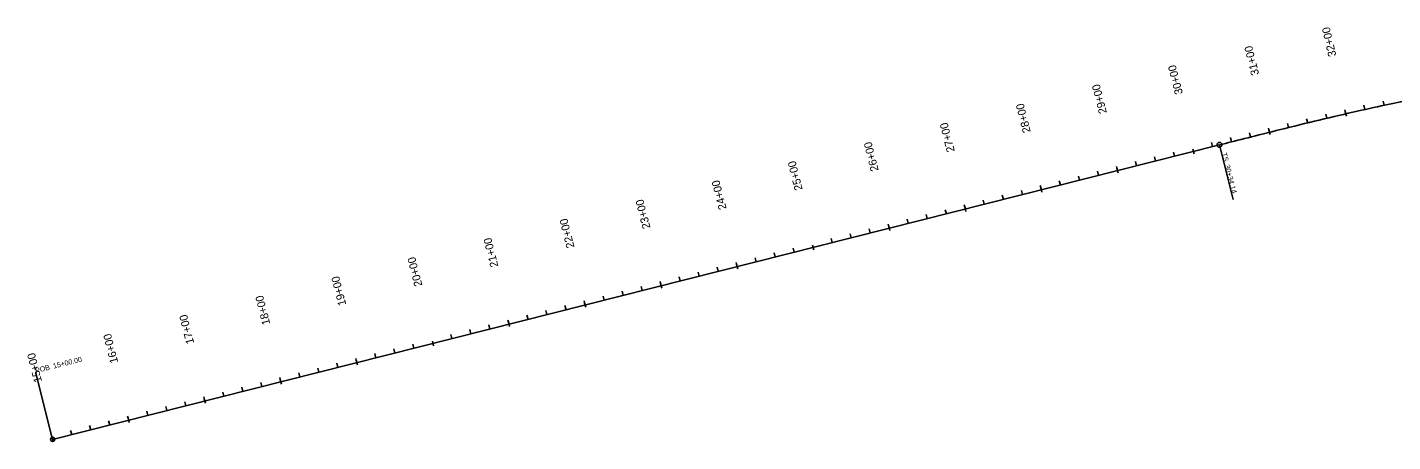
# Model space of a CAD drawing. Extents: x 21446797 to 21450291, y 8416521 to 8417382.
# Drawn here: x 21446797 to 21448538, y 8416521 to 8417049 of the extents above; entities that cross this region are included whole.
import ezdxf

# ---------------------------------------------------------------- set-up
doc = ezdxf.new("R2010")
doc.units = 0
for name, color, linetype in [('Default', 7, 'Continuous'), ('Terrain', 7, 'Continuous'), ('TextAlignment', 7, 'Continuous'), ('TextAlignmentLrg', 7, 'Continuous'), ('TextAlignmentSml', 7, 'Continuous')]:
    doc.layers.add(name, color=color, linetype=linetype)

msp = doc.modelspace()

# ---------------------------------------------------------------- linework, layer by layer
at = {"layer": 'Default'}
msp.add_line((21446829.6, 8416523.7), (21448317.1, 8416899.4), dxfattribs=at)
msp.add_open_spline([(21448317.1, 8416899.4), (21448327.1, 8416901.9), (21448347.3, 8416907), (21448387.6, 8416917.2), (21448438, 8416929.6), (21448488.6, 8416941.5), (21448529.2, 8416950.5), (21448549.5, 8416954.8), (21448559.7, 8416956.9)], degree=3, dxfattribs=at)
at = {"layer": 'Terrain'}
msp.add_line((21446829.6, 8416523.7), (21448317.1, 8416899.4), dxfattribs=at)
msp.add_open_spline([(21448317.1, 8416899.4), (21448327.1, 8416901.9), (21448347.3, 8416907), (21448387.6, 8416917.2), (21448438, 8416929.6), (21448488.6, 8416941.5), (21448529.2, 8416950.5), (21448549.5, 8416954.8), (21448559.7, 8416956.9)], degree=3, dxfattribs=at)
at = {"layer": 'TextAlignment'}
for p, q in [((21448317.1, 8416899.4), (21448334.7, 8416829.6)), ((21446829.6, 8416523.7), (21446808.3, 8416608))]:
    msp.add_line(p, q, dxfattribs=at)
for centre, radius in [((21448317.1, 8416899.4), 3.12), ((21446829.6, 8416523.7), 2.67)]:
    msp.add_circle(centre, radius, dxfattribs=at)
at = {"layer": 'TextAlignmentLrg'}
for p, q in [((21448478.1, 8416939), (21448476.9, 8416944.3)), ((21448380.9, 8416915.5), (21448379.6, 8416920.8)), ((21448283.2, 8416894), (21448284.7, 8416888.1)), ((21448187, 8416866.6), (21448185.7, 8416871.8)), ((21448090, 8416842.1), (21448088.7, 8416847.4)), ((21447993.1, 8416817.6), (21447991.8, 8416822.9)), ((21447896.1, 8416793.1), (21447894.8, 8416798.4)), ((21447798.4, 8416771.6), (21447799.9, 8416765.6)), ((21447702.2, 8416744.1), (21447700.9, 8416749.4)), ((21447605.3, 8416719.6), (21447603.9, 8416724.9)), ((21447508.3, 8416695.1), (21447507, 8416700.4)), ((21447411.4, 8416670.6), (21447410, 8416675.9)), ((21447313.7, 8416649.1), (21447315.2, 8416643.2)), ((21447217.5, 8416621.7), (21447216.1, 8416626.9)), ((21447120.5, 8416597.2), (21447119.2, 8416602.5)), ((21447023.5, 8416572.7), (21447022.2, 8416578)), ((21446926.6, 8416548.2), (21446925.2, 8416553.5)), ((21446828.9, 8416526.7), (21446830.4, 8416520.7))]:
    msp.add_line(p, q, dxfattribs=at)
at = {"layer": 'TextAlignmentSml'}
for p, q in [((21448502.5, 8416944.5), (21448501.3, 8416949.9)), ((21448526.9, 8416950), (21448525.7, 8416955.3)), ((21448429.5, 8416927.4), (21448428.2, 8416932.7)), ((21448453.8, 8416933.3), (21448452.5, 8416938.6)), ((21448477.4, 8416942), (21448478.8, 8416936)), ((21448356.7, 8416909.4), (21448355.3, 8416914.7)), ((21448380.2, 8416918.4), (21448381.7, 8416912.5)), ((21448405.2, 8416921.5), (21448403.9, 8416926.8)), ((21448308.2, 8416897.2), (21448306.9, 8416902.5)), ((21448332.4, 8416903.3), (21448331.1, 8416908.6)), ((21448211.2, 8416872.7), (21448209.9, 8416878)), ((21448235.5, 8416878.8), (21448234.1, 8416884.1)), ((21448259.7, 8416884.9), (21448258.4, 8416890.2)), ((21448283.2, 8416894), (21448284.7, 8416888.1)), ((21448138.5, 8416854.3), (21448137.2, 8416859.6)), ((21448162.8, 8416860.4), (21448161.4, 8416865.7)), ((21448186.3, 8416869.5), (21448187.8, 8416863.6)), ((21448089.3, 8416845), (21448090.8, 8416839.1)), ((21448114.3, 8416848.2), (21448112.9, 8416853.5)), ((21448017.3, 8416823.7), (21448016, 8416829)), ((21448041.6, 8416829.8), (21448040.2, 8416835.1)), ((21448065.8, 8416835.9), (21448064.5, 8416841.2)), ((21447944.6, 8416805.3), (21447943.3, 8416810.6)), ((21447968.9, 8416811.4), (21447967.5, 8416816.7)), ((21447992.3, 8416820.5), (21447993.8, 8416814.6)), ((21447871.9, 8416787), (21447870.6, 8416792.3)), ((21447895.4, 8416796), (21447896.9, 8416790.1)), ((21447920.4, 8416799.2), (21447919, 8416804.5)), ((21447823.4, 8416774.7), (21447822.1, 8416780)), ((21447847.7, 8416780.8), (21447846.3, 8416786.1)), ((21447726.5, 8416750.2), (21447725.1, 8416755.5)), ((21447750.7, 8416756.3), (21447749.4, 8416761.6)), ((21447774.9, 8416762.5), (21447773.6, 8416767.8)), ((21447798.4, 8416771.6), (21447799.9, 8416765.6)), ((21447678, 8416738), (21447676.7, 8416743.3)), ((21447701.5, 8416747.1), (21447703, 8416741.1)), ((21447604.5, 8416722.6), (21447606, 8416716.6)), ((21447629.5, 8416725.7), (21447628.2, 8416731)), ((21447653.7, 8416731.9), (21447652.4, 8416737.2)), ((21447532.6, 8416701.2), (21447531.2, 8416706.5)), ((21447556.8, 8416707.4), (21447555.5, 8416712.7)), ((21447581, 8416713.5), (21447579.7, 8416718.8)), ((21447459.8, 8416682.9), (21447458.5, 8416688.2)), ((21447484.1, 8416689), (21447482.7, 8416694.3)), ((21447507.6, 8416698.1), (21447509.1, 8416692.2)), ((21447387.1, 8416664.5), (21447385.8, 8416669.8)), ((21447410.6, 8416673.6), (21447412.1, 8416667.7)), ((21447435.6, 8416676.8), (21447434.3, 8416682.1)), ((21447338.6, 8416652.3), (21447337.3, 8416657.6)), ((21447362.9, 8416658.4), (21447361.5, 8416663.7)), ((21447241.7, 8416627.8), (21447240.4, 8416633.1)), ((21447265.9, 8416633.9), (21447264.6, 8416639.2)), ((21447290.2, 8416640), (21447288.8, 8416645.3)), ((21447313.7, 8416649.1), (21447315.2, 8416643.2)), ((21447193.2, 8416615.5), (21447191.9, 8416620.8)), ((21447216.7, 8416624.6), (21447218.2, 8416618.7)), ((21447119.7, 8416600.1), (21447121.2, 8416594.2)), ((21447144.7, 8416603.3), (21447143.4, 8416608.6)), ((21447169, 8416609.4), (21447167.6, 8416614.7)), ((21447047.8, 8416578.8), (21447046.4, 8416584.1)), ((21447072, 8416584.9), (21447070.7, 8416590.2)), ((21447096.3, 8416591), (21447094.9, 8416596.3)), ((21446975.1, 8416560.4), (21446973.7, 8416565.7)), ((21446999.3, 8416566.6), (21446998, 8416571.8)), ((21447022.8, 8416575.6), (21447024.3, 8416569.7)), ((21446902.3, 8416542.1), (21446901, 8416547.4)), ((21446925.8, 8416551.2), (21446927.3, 8416545.2)), ((21446950.8, 8416554.3), (21446949.5, 8416559.6)), ((21446853.9, 8416529.8), (21446852.5, 8416535.1)), ((21446878.1, 8416535.9), (21446876.8, 8416541.2)), ((21446828.9, 8416526.7), (21446830.4, 8416520.7))]:
    msp.add_line(p, q, dxfattribs=at)

# ---------------------------------------------------------------- texts
at = {"layer": 'TextAlignment'}
for s, rotation, p in [('TS', 284.1757, (21448319.9, 8416888.6)), ('30+34.14', 284.1757, (21448323.8, 8416873.3)), ('POB ', 14.1757, (21446808.3, 8416608.2)), ('15+00.00', 14.1757, (21446831, 8416613.9))]:
    msp.add_text(s, height=6.48, rotation=rotation, dxfattribs=at).set_placement(p)
at = {"layer": 'TextAlignmentLrg'}
for s, p in [('30+00', (21448270.5, 8416965)), ('25+00', (21447785.8, 8416842.6)), ('20+00', (21447301, 8416720.1)), ('15+00', (21446816.2, 8416597.7))]:
    msp.add_text(s, height=10.2, rotation=104.1757, dxfattribs=at).set_placement(p)
at = {"layer": 'TextAlignmentSml'}
for s, rotation, p in [('32+00', 103.058, (21448466.1, 8417013.2)), ('31+00', 103.9995, (21448367.7, 8416989.5)), ('30+00', 104.1757, (21448270.5, 8416965)), ('29+00', 104.1757, (21448173.6, 8416940.5)), ('28+00', 104.1757, (21448076.6, 8416916)), ('27+00', 104.1757, (21447979.7, 8416891.5)), ('26+00', 104.1757, (21447882.7, 8416867)), ('25+00', 104.1757, (21447785.8, 8416842.6)), ('24+00', 104.1757, (21447688.8, 8416818.1)), ('23+00', 104.1757, (21447591.8, 8416793.6)), ('22+00', 104.1757, (21447494.9, 8416769.1)), ('21+00', 104.1757, (21447397.9, 8416744.6)), ('20+00', 104.1757, (21447301, 8416720.1)), ('19+00', 104.1757, (21447204, 8416695.6)), ('18+00', 104.1757, (21447107.1, 8416671.1)), ('17+00', 104.1757, (21447010.1, 8416646.6)), ('16+00', 104.1757, (21446913.2, 8416622.2)), ('15+00', 104.1757, (21446816.2, 8416597.7))]:
    msp.add_text(s, height=10.2, rotation=rotation, dxfattribs=at).set_placement(p)

doc.saveas('drawing.dxf')
